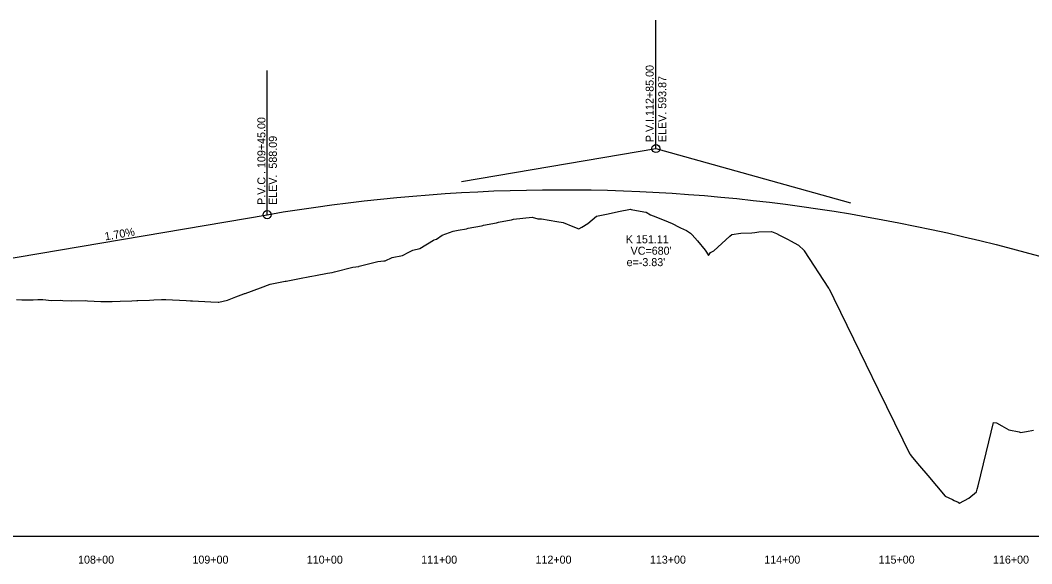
# Model space of a CAD drawing. Extents: x 634057 to 641016, y 287858 to 292331.
# Drawn here: x 638345 to 639229, y 288821 to 289296 of the extents above; entities that cross this region are included whole.
import ezdxf

# ---------------------------------------------------------------- set-up
doc = ezdxf.new("R2010")
doc.units = 0
for name, color, linetype in [('R_Axis', 7, 'Continuous'), ('R_Axis Annot', 7, 'Continuous'), ('R_No Plot', 7, 'Continuous'), ('R_Vert Alg', 7, 'Continuous'), ('R_Vert Alg Annot', 7, 'Continuous')]:
    doc.layers.add(name, color=color, linetype=linetype)

msp = doc.modelspace()

# ---------------------------------------------------------------- linework, layer by layer
at = {"layer": 'R_Axis'}
msp.add_line((637415.8, 288845.53), (640715.8, 288845.53), dxfattribs=at)
at = {"layer": 'R_No Plot'}
msp.add_lwpolyline([(638341.77, 289052.37), (638346.31, 289051.99), (638356.11, 289052.16), (638360.45, 289052.24), (638364.63, 289052.33), (638372.27, 289051.6), (638380.19, 289051.65), (638382.06, 289051.55), (638390.07, 289051.13), (638402.15, 289051.34), (638403.67, 289051.24), (638415.31, 289050.51), (638423.5, 289050.6), (638425.28, 289050.65), (638432.41, 289050.87), (638442.41, 289051.18), (638446.88, 289051.45), (638447.67, 289051.5), (638458.1, 289051.83), (638461.6, 289052.05), (638468.49, 289052.24), (638472.34, 289052.36), (638490.1, 289051.35), (638493.95, 289051.14), (638495.41, 289051.19), (638511.71, 289050.27), (638517.92, 289049.95), (638518.54, 289049.97), (638526.05, 289051.76), (638533.32, 289054.6), (638540.47, 289057.39), (638540.89, 289057.45), (638541.55, 289057.55), (638554.93, 289062.55), (638563.42, 289065.72), (638575.08, 289068.08), (638576.54, 289068.29), (638577.52, 289068.42), (638589.08, 289070.71), (638598.15, 289072.51), (638599.86, 289072.84), (638603.11, 289073.28), (638613.55, 289075.31), (638617.74, 289075.86), (638619.76, 289076.4), (638635.84, 289080.68), (638641.05, 289081.29), (638641.37, 289081.38), (638657.64, 289085.62), (638662.98, 289086.16), (638663.88, 289086.25), (638670.19, 289089.08), (638679.31, 289090.87), (638684.59, 289093.59), (638688.26, 289095.48), (638694.37, 289096.86), (638706.2, 289104.04), (638706.94, 289104.49), (638708.86, 289104.99), (638713.8, 289108.64), (638723.47, 289112.07), (638727.81, 289112.82), (638735.25, 289114.1), (638736.68, 289114.63), (638748.37, 289116.68), (638749.42, 289117.06), (638749.87, 289117.22), (638761.49, 289119.29), (638763.05, 289119.82), (638771.03, 289121.26), (638774.62, 289121.91), (638776.22, 289122.44), (638792.64, 289124.13), (638792.69, 289124.14), (638797.61, 289122.75), (638800.67, 289122.78), (638814.25, 289120.46), (638819.72, 289119.51), (638828.03, 289116.25), (638833.25, 289114.2), (638835.86, 289115.66), (638841.19, 289118.64), (638848.74, 289125.14), (638857.47, 289126.94), (638859.07, 289127.27), (638868.11, 289129.13), (638878.68, 289131.16), (638879.08, 289131.09), (638890.18, 289128.91), (638892.1, 289128.73), (638895.9, 289126.39), (638900.69, 289124.52), (638911.51, 289120.27), (638915.08, 289118.83), (638921.12, 289115.48), (638922.3, 289114.98), (638927.5, 289112.76), (638931.02, 289110.43), (638932.55, 289108.9), (638937.22, 289103.67), (638943.91, 289095.34), (638945.12, 289093.82), (638946.7, 289090.69), (638948.61, 289093.29), (638951.32, 289094.87), (638965.52, 289107.73), (638967.2, 289109.25), (638975.08, 289110.15), (638984.51, 289110.67), (638987.13, 289110.95), (638990.85, 289111.35), (639001.7, 289111.87), (639006.27, 289109.93), (639008.74, 289108.63), (639016.3, 289104.63), (639018.51, 289103.68), (639025.45, 289099.78), (639030.35, 289095.03), (639030.46, 289094.92), (639051.81, 289062.2), (639051.95, 289061.9), (639054.17, 289057.44), (639056.26, 289053.24), (639073.56, 289017.93), (639095.17, 288973.81), (639116.78, 288929.65), (639122.28, 288918.4), (639122.67, 288917.57), (639123.05, 288916.77), (639125.26, 288914.23), (639131.26, 288907.12), (639138.39, 288898.66), (639153.69, 288880.48), (639160, 288877.54), (639161.55, 288876.82), (639165.03, 288875.19), (639166.34, 288874.38), (639174.5, 288878.85), (639180.96, 288884.39), (639181.61, 288886.7), (639182.43, 288889.58), (639191.78, 288927.82), (639195.94, 288944.83), (639196.09, 288944.9), (639198.47, 288944.55), (639203.22, 288941.93), (639209.45, 288938.51), (639218.42, 288936.63), (639219.44, 288936.16), (639224.83, 288937.12), (639230.98, 288938.23)], dxfattribs=at)
at = {"layer": 'R_Vert Alg'}
for p, q in [((638900.8, 289184.25), (638900.8, 289296.34)), ((638560.8, 289126.45), (638560.8, 289252.45)), ((638730.8, 289155.35), (638900.8, 289184.25)), ((638900.8, 289184.25), (639070.8, 289136.65)), ((638310.62, 289083.92), (638560.8, 289126.45))]:
    msp.add_line(p, q, dxfattribs=at)
msp.add_lwpolyline([(638560.8, 289126.45), (638574.97, 289128.79), (638589.13, 289131), (638603.3, 289133.08), (638617.47, 289135.02), (638631.63, 289136.83), (638645.8, 289138.51), (638659.97, 289140.05), (638674.13, 289141.46), (638688.3, 289142.74), (638702.47, 289143.89), (638716.63, 289144.9), (638730.8, 289145.79), (638744.97, 289146.53), (638759.13, 289147.15), (638773.3, 289147.63), (638787.47, 289147.98), (638801.63, 289148.2), (638815.8, 289148.28), (638829.97, 289148.23), (638844.13, 289148.05), (638858.3, 289147.74), (638872.47, 289147.29), (638886.63, 289146.71), (638914.97, 289145.15), (638929.13, 289144.17), (638943.3, 289143.06), (638957.47, 289141.82), (638971.63, 289140.44), (638985.8, 289138.93), (638999.97, 289137.29), (639014.13, 289135.51), (639028.3, 289133.61), (639042.47, 289131.57), (639056.63, 289129.39), (639070.8, 289127.09), (639084.97, 289124.65), (639099.13, 289122.07), (639113.3, 289119.37), (639127.47, 289116.53), (639141.63, 289113.56), (639155.8, 289110.46), (639169.97, 289107.22), (639184.13, 289103.85), (639198.3, 289100.35), (639212.47, 289096.72), (639226.63, 289092.95), (639240.8, 289089.05)], dxfattribs=at)
for centre in [(638900.8, 289184.25), (638560.8, 289126.45)]:
    msp.add_circle(centre, 3.5, dxfattribs=at)

# ---------------------------------------------------------------- texts
at = {"layer": 'R_Axis Annot'}
for s, p in [('108+00', (638395.49, 288821.53)), ('109+00', (638495.49, 288821.53)), ('110+00', (638595.49, 288821.53)), ('111+00', (638695.49, 288821.53)), ('112+00', (638795.49, 288821.53)), ('113+00', (638895.49, 288821.53)), ('114+00', (638995.49, 288821.53)), ('115+00', (639095.49, 288821.53)), ('116+00', (639195.49, 288821.53))]:
    msp.add_text(s, height=7, dxfattribs=at).set_placement(p)
at = {"layer": 'R_Vert Alg Annot'}
for s, rotation, p in [('P.V.I.112+85.00', 90, (638898.8, 289189.82)), ('ELEV. 593.87', 90, (638909.8, 289189.82)), ('P.V.C . 109+45.00', 90, (638559.3, 289134.95)), ('ELEV.  588.09', 90, (638569.3, 289134.95)), ('1.70%', 9.64805, (638419.35, 289103.92))]:
    msp.add_text(s, height=7, rotation=rotation, dxfattribs=at).set_placement(p)
for s, p in [('K 151.11', (638874.48, 289101.47)), ("VC=680'", (638878.63, 289091.47)), ("e=-3.83'", (638875.13, 289081.47))]:
    msp.add_text(s, height=7, dxfattribs=at).set_placement(p)

doc.saveas('drawing.dxf')
